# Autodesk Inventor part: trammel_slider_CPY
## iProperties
Created: 2008-11
Part Number: trammel_slider_CPY
Document SubType Name: Modeling
Designer: Lochan
Density: 1 g/cm^3
Author: Lochan
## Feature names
1. Extrusion1
2. Extrusion2
